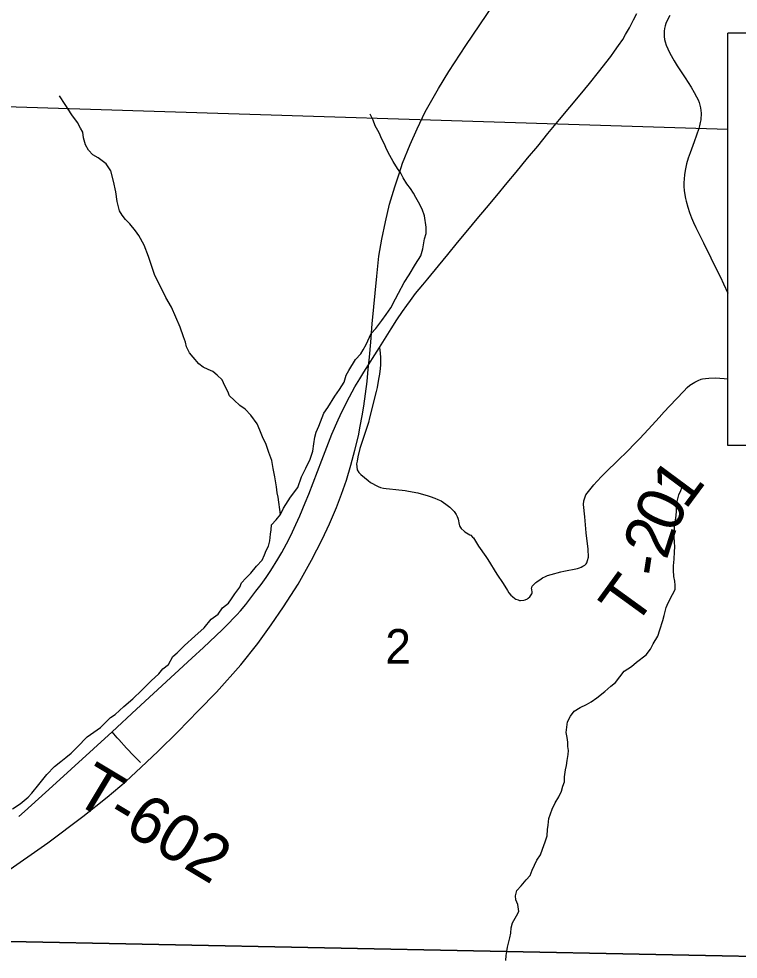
# Model space of a CAD drawing. Extents: x -1.2 to 34, y -8.5 to 22.
# Drawn here: x 4.454 to 5.325, y 15.609 to 16.749 of the extents above; entities that cross this region are included whole.
import ezdxf

# ---------------------------------------------------------------- set-up
doc = ezdxf.new("R2010")
doc.units = 0
for name, color, linetype in [('GM_X_County_Road', 7, 'Continuous'), ('GM_X_Minor_River', 7, 'Continuous'), ('GM_X_Rail_Line', 7, 'Continuous'), ('GM_X_Section', 7, 'Continuous'), ('GM_X_Section_Text', 7, 'Continuous'), ('GM_X_State_Route', 7, 'Continuous'), ('GM_X_Township_Road', 7, 'Continuous'), ('GM_X_Township_Road_Text', 7, 'Continuous'), ('SH_Text', 7, 'Continuous')]:
    doc.layers.add(name, color=color, linetype=linetype)

msp = doc.modelspace()

# ---------------------------------------------------------------- linework, layer by layer
at = {"layer": 'GM_X_County_Road'}
for points in [[(5.2426, 16.7527), (5.2396, 16.7471), (5.2377, 16.743), (5.2367, 16.7398), (5.236, 16.7367), (5.2356, 16.7335), (5.2358, 16.7269), (5.2362, 16.7236), (5.2369, 16.7207), (5.2382, 16.7167), (5.2402, 16.712), (5.2427, 16.707), (5.2478, 16.6976), (5.2515, 16.6917), (5.261, 16.6771), (5.2683, 16.6657), (5.2721, 16.6592), (5.275, 16.6539), (5.2767, 16.6504), (5.278, 16.6469), (5.279, 16.6437), (5.2797, 16.6407), (5.2801, 16.6375), (5.2804, 16.6341), (5.28, 16.626), (5.2795, 16.623), (5.2785, 16.6188), (5.2775, 16.6155), (5.2719, 16.5995), (5.2671, 16.5862), (5.2648, 16.5794), (5.2629, 16.5726), (5.2611, 16.5646), (5.2603, 16.5592), (5.2598, 16.5546), (5.2596, 16.5498), (5.2597, 16.5451), (5.2601, 16.5404), (5.2607, 16.5352), (5.2616, 16.5309), (5.2624, 16.5273), (5.2643, 16.5202), (5.2663, 16.5138), (5.2689, 16.5072), (5.2711, 16.5018), (5.2742, 16.4956), (5.2835, 16.4768), (5.3012, 16.4407)], [(5.3012, 16.4407), (5.3039, 16.4353), (5.3076, 16.4272), (5.3129, 16.4159)]]:
    msp.add_lwpolyline(points, dxfattribs=at)
at = {"layer": 'GM_X_Minor_River'}
for points in [[(4.7708, 16.1478), (4.7679, 16.1687), (4.7667, 16.174), (4.7658, 16.1812), (4.7637, 16.1934), (4.7617, 16.2036), (4.7604, 16.2131), (4.7565, 16.223), (4.7529, 16.2336), (4.7498, 16.24), (4.7459, 16.2498), (4.7423, 16.2578), (4.735, 16.2683), (4.7281, 16.2754), (4.7216, 16.2799), (4.7147, 16.2863), (4.7089, 16.2915), (4.7069, 16.2968), (4.7034, 16.3036), (4.6999, 16.3108), (4.6942, 16.3164), (4.6888, 16.3209), (4.6831, 16.3235), (4.677, 16.3264), (4.672, 16.3302), (4.6651, 16.3384), (4.6604, 16.3437), (4.6569, 16.3509), (4.6557, 16.3566), (4.6533, 16.363), (4.649, 16.3747), (4.6388, 16.3989), (4.6318, 16.4106), (4.6268, 16.4208), (4.6229, 16.4284), (4.6182, 16.4386), (4.611, 16.4606), (4.6055, 16.4742), (4.5989, 16.4859), (4.5951, 16.4915), (4.5881, 16.5002), (4.5831, 16.5054), (4.5789, 16.5107), (4.5758, 16.5156), (4.573, 16.527), (4.5713, 16.5387), (4.5684, 16.5516), (4.5652, 16.5642), (4.5594, 16.5728), (4.5499, 16.5799), (4.5434, 16.5836), (4.538, 16.5892), (4.5345, 16.5957), (4.5321, 16.6044), (4.5312, 16.6112), (4.5285, 16.6161), (4.5246, 16.6229), (4.5181, 16.632), (4.5099, 16.6448), (4.503, 16.6553)], [(4.6782, 16.0105), (4.6867, 16.0209), (4.6953, 16.0268), (4.7005, 16.0345), (4.7076, 16.0403), (4.7114, 16.0457), (4.7154, 16.0514), (4.7214, 16.0595), (4.7236, 16.0649), (4.7288, 16.0707), (4.7348, 16.0765), (4.7415, 16.0849), (4.7485, 16.0923), (4.7515, 16.0988), (4.7533, 16.1042), (4.7562, 16.1095), (4.7577, 16.116), (4.7587, 16.124), (4.7594, 16.129), (4.76, 16.1351), (4.7656, 16.1413), (4.7708, 16.1478), (4.7745, 16.1555), (4.783, 16.1686), (4.7919, 16.1805), (4.7963, 16.1935), (4.8014, 16.2039), (4.8066, 16.2146), (4.8098, 16.2246), (4.8112, 16.2333), (4.8123, 16.2413), (4.8141, 16.2475), (4.8174, 16.2547), (4.8232, 16.2704), (4.828, 16.2774), (4.8365, 16.2912), (4.8421, 16.2993), (4.848, 16.3081), (4.8505, 16.3165), (4.8535, 16.3223), (4.8616, 16.3354), (4.8683, 16.3423), (4.8709, 16.3473), (4.8746, 16.3538), (4.8805, 16.3669), (4.8861, 16.373), (4.8935, 16.3827), (4.8987, 16.39), (4.9046, 16.3984), (4.9102, 16.4092), (4.9138, 16.4161), (4.9205, 16.4291), (4.9268, 16.438), (4.9342, 16.4511), (4.9408, 16.4611), (4.9433, 16.4698), (4.9451, 16.4817), (4.9472, 16.4882), (4.9471, 16.4958), (4.9454, 16.5098), (4.9423, 16.5178), (4.938, 16.5261), (4.9349, 16.5318), (4.9318, 16.537), (4.9283, 16.5427), (4.924, 16.5483), (4.9194, 16.5559), (4.9166, 16.5616), (4.9124, 16.5672), (4.9074, 16.5755), (4.9031, 16.5827), (4.8996, 16.5898), (4.8964, 16.5974), (4.8937, 16.6027), (4.8902, 16.6103), (4.8855, 16.6189), (4.8832, 16.6258), (4.8796, 16.6329)], [(5.2481, 16.1323), (5.2495, 16.1407), (5.2502, 16.1464), (5.2505, 16.1518), (5.2508, 16.1582), (5.2515, 16.1636), (5.2536, 16.1716), (5.2558, 16.177), (5.257, 16.1801)], [(5.0437, 15.6073), (5.0444, 15.6131), (5.0451, 15.618), (5.0458, 15.6233), (5.0472, 15.6283), (5.0486, 15.6348), (5.0497, 15.6402), (5.0504, 15.6466), (5.0518, 15.6527), (5.0566, 15.6612), (5.0595, 15.6666), (5.0583, 15.6749), (5.0559, 15.6806), (5.0555, 15.6855), (5.0573, 15.692), (5.0625, 15.6978), (5.0684, 15.7051), (5.0733, 15.7102), (5.0758, 15.7167), (5.0814, 15.7286), (5.0858, 15.7351), (5.0884, 15.742), (5.0916, 15.7508), (5.0938, 15.7584), (5.0944, 15.7661), (5.0951, 15.771), (5.0961, 15.7794), (5.1001, 15.7905), (5.1038, 15.7982), (5.1079, 15.8055), (5.1112, 15.8124), (5.113, 15.8185), (5.1148, 15.8239), (5.1151, 15.8299), (5.1161, 15.8383), (5.1172, 15.8437), (5.1182, 15.8494), (5.1192, 15.8567), (5.1196, 15.8616), (5.1191, 15.8666), (5.119, 15.8719), (5.1182, 15.8776), (5.117, 15.8836), (5.1176, 15.8901), (5.1187, 15.8966), (5.122, 15.9031), (5.1268, 15.9093), (5.1339, 15.9136), (5.1415, 15.9175), (5.1471, 15.9206), (5.1542, 15.9257), (5.1636, 15.9331), (5.171, 15.9397), (5.1767, 15.9439), (5.1871, 15.9578), (5.1961, 15.9633), (5.202, 15.9687), (5.214, 15.9776), (5.2192, 15.9846), (5.2225, 15.9911), (5.2281, 16.0003), (5.2306, 16.008), (5.2342, 16.0194), (5.2357, 16.0255), (5.2382, 16.0351), (5.2404, 16.0408), (5.2459, 16.0508), (5.2492, 16.057), (5.2492, 16.0619), (5.2487, 16.0668), (5.2475, 16.0725), (5.247, 16.0801), (5.2469, 16.0855), (5.2476, 16.0935), (5.2482, 16.1026), (5.2485, 16.1087), (5.2484, 16.114), (5.2479, 16.1201), (5.2481, 16.1323)], [(4.4462, 15.7911), (4.4552, 15.797), (4.465, 15.8051), (4.4694, 15.8101), (4.478, 15.8205), (4.4877, 15.8325), (4.497, 15.8422), (4.5045, 15.8484), (4.5108, 15.853), (4.5172, 15.8584), (4.5243, 15.8658), (4.5366, 15.8782), (4.5527, 15.8894), (4.5647, 15.9018), (4.5703, 15.9053), (4.5811, 15.915), (4.592, 15.9243), (4.6028, 15.9347), (4.614, 15.946), (4.6233, 15.9545), (4.6282, 15.9606), (4.6349, 15.9661), (4.6404, 15.9757), (4.6457, 15.9799), (4.6543, 15.9888), (4.667, 16.0001), (4.6782, 16.0105)]]:
    msp.add_lwpolyline(points, dxfattribs=at)
at = {"layer": 'GM_X_Rail_Line'}
msp.add_lwpolyline([(4.435, 15.7123), (4.4888, 15.7499), (4.5314, 15.7817), (4.5609, 15.8052), (4.5837, 15.8247), (4.6015, 15.8411), (4.6226, 15.8609), (4.6463, 15.8844), (4.6716, 15.9101), (4.6931, 15.9324), (4.7228, 15.9654), (4.7431, 15.9913), (4.7594, 16.0138), (4.7744, 16.0357), (4.792, 16.0634), (4.8083, 16.0924), (4.8214, 16.1175), (4.8303, 16.1363), (4.8385, 16.1561), (4.8446, 16.1723), (4.8508, 16.1893), (4.856, 16.2077), (4.8609, 16.2258), (4.8651, 16.2432), (4.8675, 16.2549), (4.8698, 16.2673), (4.8716, 16.279), (4.8757, 16.3089), (4.8772, 16.3239), (4.8785, 16.3386), (4.8802, 16.3567), (4.8819, 16.3788), (4.8873, 16.4367), (4.89, 16.461), (4.8936, 16.4815), (4.898, 16.5025), (4.903, 16.5238), (4.9092, 16.545), (4.9149, 16.5618), (4.9188, 16.5735), (4.9278, 16.5963), (4.9362, 16.6151), (4.9462, 16.6359), (4.9621, 16.6642), (4.9749, 16.6847), (4.9954, 16.716), (5.0631, 16.8167)], dxfattribs=at)
at = {"layer": 'GM_X_Section'}
msp.add_lwpolyline([(5.4357, 16.2314), (5.428, 15.6979), (5.4262, 15.6104), (4.4223, 15.6306), (4.4375, 16.6421), (5.3129, 16.6148)], dxfattribs=at)
msp.add_lwpolyline([(4.4223, 15.6306), (5.4262, 15.6104), (5.4125, 14.6774), (5.4116, 14.6095), (4.409, 14.6166)], close=True, dxfattribs=at)
at = {"layer": 'GM_X_State_Route'}
msp.add_lwpolyline([(4.4535, 15.7816), (4.4606, 15.7878), (4.4946, 15.8183), (4.5669, 15.8844), (4.5963, 15.9118), (4.6632, 15.9734), (4.6773, 15.9865), (4.7, 16.0078), (4.7042, 16.0119), (4.7179, 16.0262), (4.7223, 16.0311), (4.7287, 16.0387), (4.7348, 16.0466), (4.741, 16.0546), (4.7472, 16.063), (4.7533, 16.0714), (4.7589, 16.0798), (4.7674, 16.0936), (4.7722, 16.1018), (4.7781, 16.1122), (4.7817, 16.119), (4.7854, 16.1269), (4.7893, 16.1354), (4.794, 16.146), (4.8008, 16.1619), (4.8049, 16.1724), (4.8208, 16.2137), (4.833, 16.2451), (4.8406, 16.2624), (4.8453, 16.2728), (4.8544, 16.2903), (4.861, 16.3024), (4.867, 16.3123), (4.8719, 16.3203), (4.8906, 16.35), (4.9047, 16.3729), (4.9119, 16.3836), (4.9187, 16.3939), (4.9237, 16.4011), (4.9281, 16.4071), (4.9345, 16.4154), (4.9434, 16.426), (4.9494, 16.4335), (4.9621, 16.4493), (4.9734, 16.463), (4.9854, 16.4773), (4.9977, 16.4922), (5.0092, 16.5059), (5.0202, 16.5193), (5.0329, 16.5343), (5.0454, 16.5496), (5.0562, 16.5628), (5.0702, 16.5798), (5.0824, 16.5941), (5.0948, 16.6094), (5.1088, 16.6265), (5.1214, 16.6415), (5.1338, 16.6564), (5.1451, 16.6701), (5.1562, 16.6837), (5.171, 16.703), (5.1756, 16.7091), (5.1805, 16.7163), (5.1855, 16.7236), (5.1889, 16.7294), (5.1937, 16.7375), (5.1987, 16.7471), (5.2026, 16.7551)], dxfattribs=at)
at = {"layer": 'GM_X_Township_Road'}
for points in [[(4.8906, 16.35), (4.8915, 16.3434), (4.8919, 16.3381), (4.8921, 16.3334), (4.8919, 16.3293), (4.8915, 16.3245), (4.8906, 16.318), (4.8896, 16.3118), (4.8878, 16.3018), (4.8866, 16.2966), (4.8787, 16.2647), (4.8773, 16.2594), (4.8671, 16.2279), (4.8644, 16.2176), (4.8635, 16.2122), (4.863, 16.209), (4.8637, 16.2017), (4.8655, 16.1985), (4.868, 16.1961)], [(4.868, 16.1961), (4.8724, 16.1925), (4.8768, 16.1889), (4.8797, 16.1867), (4.8822, 16.1851), (4.8857, 16.1832), (4.8892, 16.1815), (4.892, 16.1805), (4.8956, 16.1797), (4.8987, 16.1792), (4.9028, 16.1789), (4.9104, 16.1781), (4.9219, 16.1767), (4.926, 16.1759), (4.9372, 16.1738), (4.9498, 16.1704), (4.9523, 16.1696), (4.9578, 16.1676), (4.9613, 16.1661), (4.9653, 16.1641), (4.9684, 16.1622), (4.9711, 16.1604), (4.9759, 16.1567), (4.978, 16.1547), (4.9813, 16.1513), (4.9822, 16.1501), (4.9836, 16.1476), (4.9849, 16.1453), (4.9856, 16.1432), (4.986, 16.142), (4.9873, 16.1355), (4.9878, 16.1341), (4.989, 16.1318), (4.9897, 16.1309), (4.9932, 16.1276), (4.994, 16.1269), (5.0002, 16.1232), (5.0013, 16.1225), (5.0036, 16.1204), (5.0045, 16.1193), (5.007, 16.1156), (5.0094, 16.1115), (5.0108, 16.1092), (5.0196, 16.0967), (5.0221, 16.093), (5.0331, 16.0754), (5.0404, 16.0639), (5.0458, 16.0555), (5.0476, 16.0529), (5.05, 16.05), (5.0518, 16.0482), (5.0546, 16.0461), (5.0559, 16.0453), (5.0587, 16.0441), (5.0603, 16.0436), (5.0616, 16.0434), (5.0657, 16.0437), (5.0671, 16.0442), (5.0699, 16.0455), (5.071, 16.0462), (5.073, 16.048), (5.0739, 16.0491), (5.0752, 16.0516), (5.0756, 16.0527), (5.0757, 16.0537), (5.0752, 16.0569), (5.0751, 16.0583), (5.0753, 16.0594), (5.0759, 16.0608), (5.0766, 16.0618), (5.08, 16.0651), (5.0815, 16.0663), (5.0867, 16.0699), (5.0881, 16.0708), (5.092, 16.0727), (5.0944, 16.0736), (5.0989, 16.0751), (5.1106, 16.0782), (5.114, 16.079), (5.1306, 16.0824), (5.1332, 16.0832), (5.1351, 16.084), (5.1371, 16.0851), (5.1395, 16.0865), (5.141, 16.088), (5.142, 16.0893), (5.1429, 16.0921), (5.1438, 16.0962), (5.1434, 16.1058), (5.1413, 16.1256), (5.1395, 16.1447), (5.1381, 16.1597), (5.1384, 16.1642), (5.1395, 16.1681), (5.1409, 16.1717), (5.1505, 16.1836), (5.1541, 16.1878), (5.16, 16.194), (5.1657, 16.1997), (5.1789, 16.2125), (5.1919, 16.2251), (5.1994, 16.2328), (5.2058, 16.2396), (5.2165, 16.2512), (5.2296, 16.2653), (5.2358, 16.272), (5.2423, 16.279), (5.2595, 16.2973), (5.2637, 16.3015), (5.2668, 16.3043), (5.2687, 16.3057), (5.2727, 16.3081), (5.2769, 16.3102), (5.2804, 16.3116), (5.282, 16.3121), (5.2859, 16.3127), (5.2898, 16.3131), (5.2977, 16.3134), (5.303, 16.3131), (5.3084, 16.3127), (5.3129, 16.3121)], [(4.6012, 15.847), (4.5932, 15.8553), (4.5843, 15.8647), (4.5748, 15.8752), (4.573, 15.8771), (4.5669, 15.8844)]]:
    msp.add_lwpolyline(points, dxfattribs=at)
at = {"layer": 'SH_Text'}
for p, q in [((6.6707, 16.731), (5.3129, 16.731)), ((5.3129, 16.2314), (5.3129, 16.731)), ((6.7905, 16.2314), (5.3129, 16.2314))]:
    msp.add_line(p, q, dxfattribs=at)

# ---------------------------------------------------------------- texts
at = {"layer": 'GM_X_Section_Text'}
msp.add_text('2', height=0.0419, rotation=0, dxfattribs=at).set_placement((4.8977, 15.967))
at = {"layer": 'GM_X_Township_Road_Text'}
for s, height, rotation, p in [('1', 0.0568, 53.4351, (5.2615, 16.1524)), ('0', 0.0568, 65.6069, (5.2487, 16.1233)), ('2', 0.0568, 72.067, (5.2385, 16.0916)), ('-', 0.0568, 81.1849, (5.2355, 16.0708)), ('T', 0.0568, 54.0533, (5.1995, 16.0096)), ('T-602', 0.05682, 329.0364, (4.5176, 15.8008))]:
    msp.add_text(s, height=height, rotation=rotation, dxfattribs=at).set_placement(p)

doc.saveas('drawing.dxf')
